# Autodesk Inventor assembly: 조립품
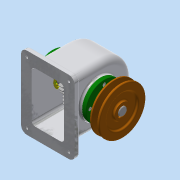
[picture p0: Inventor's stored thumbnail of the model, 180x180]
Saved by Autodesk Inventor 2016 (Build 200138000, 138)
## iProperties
Created: 2018-11
Part Number: 조립품
Material: 일반
Document SubType Name: Assembly
Designer: user
Author: user
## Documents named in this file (14)
- C:\Users\user\Desktop\481111V1008\조립품.iam
- C:\Users\user\Desktop\481111V1008\V-벨트풀리.ipt
- C:\Users\user\Desktop\481111V1008\뒤커버.ipt
- C:\Users\user\Desktop\481111V1008\멈춤나사 M4.ipt
- C:\Users\user\Desktop\481111V1008\베어링 6203.ipt
- C:\Users\user\Desktop\481111V1008\본체.ipt
- C:\Users\user\Desktop\481111V1008\볼트 M4.ipt
- C:\Users\user\Desktop\481111V1008\부시.ipt
- C:\Users\user\Desktop\481111V1008\스퍼기어.ipt
- C:\Users\user\Desktop\481111V1008\앞커버.ipt
- C:\Users\user\Desktop\481111V1008\오일 실 28 40 8.ipt
- C:\Users\user\Desktop\481111V1008\축.ipt
- C:\Users\user\Desktop\481111V1008\키 5x5x18.ipt
- C:\Users\user\Desktop\481111V1008\키 6x6x22.ipt
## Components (1 placed, 1 different names)
1. V-벨트풀리:1
